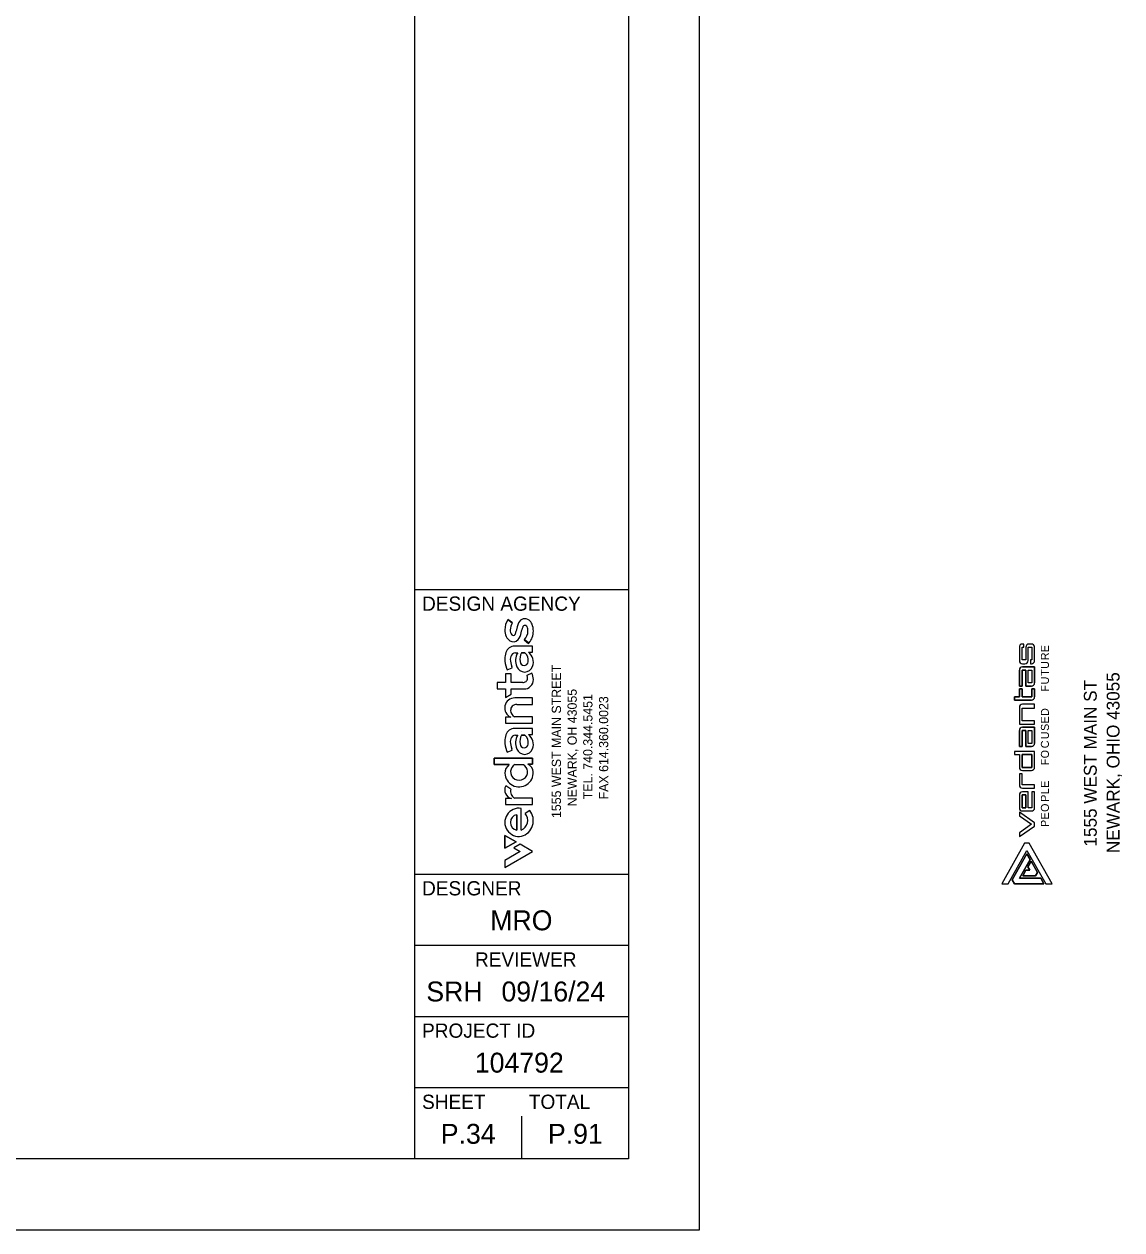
# Model space of a CAD drawing. Extents: x -0.2 to 37, y 0 to 22.
# Drawn here: x 29.25 to 36.97, y 0 to 8.47 of the extents above; entities that cross this region are included whole.
import ezdxf

# ---------------------------------------------------------------- set-up
doc = ezdxf.new("R2010")
doc.units = 0
for name, color, linetype in [('Default', 7, 'Continuous'), ('PF_P_Text_Curve', 7, 'Continuous'), ('SH_Border', 7, 'Continuous'), ('SH_Cut_Line', 7, 'Continuous'), ('SH_Data', 7, 'Continuous'), ('SH_Text', 7, 'Continuous')]:
    doc.layers.add(name, color=color, linetype=linetype)

msp = doc.modelspace()

# ---------------------------------------------------------------- linework, layer by layer
at = {"layer": 'Default'}
for p, q in [((36.2462, 4.0936), (36.2462, 4.0008)), ((36.3306, 4.1161), (36.3137, 4.1161)), ((36.3531, 4.0008), (36.3531, 4.0936)), ((36.2687, 3.9783), (36.2856, 3.9783)), ((36.2687, 3.2273), (36.3306, 3.2273)), ((36.2462, 3.0557), (36.2462, 2.9657)), ((36.2687, 2.9432), (36.3306, 2.9432)), ((36.1957, 2.4593), (36.299, 2.6425)), ((36.299, 2.6425), (36.3216, 2.6024)), ((36.3216, 2.6024), (36.2475, 2.471)), ((36.2113, 2.4316), (36.1957, 2.4593)), ((36.2475, 2.471), (36.3958, 2.471)), ((36.3958, 2.471), (36.418, 2.4316)), ((36.418, 2.4316), (36.2113, 2.4316))]:
    msp.add_line(p, q, dxfattribs=at)
for points in [[(36.2912, 4.0936), (36.2912, 4.0064), (36.2659, 4.0064), (36.2659, 4.0936), (36.2772, 4.0936), (36.2772, 4.1161), (36.2687, 4.1161)], [(36.3081, 4.0008), (36.3081, 4.0936), (36.3334, 4.0936), (36.3334, 4.0064), (36.325, 4.0064), (36.325, 3.9783), (36.3306, 3.9783)], [(36.2462, 3.9333), (36.2462, 3.8208), (36.2659, 3.8208), (36.2659, 3.9333), (36.2912, 3.9333), (36.2912, 3.8208), (36.3306, 3.8208)], [(36.3531, 3.8433), (36.3531, 3.9558), (36.2687, 3.9558)], [(36.3531, 3.7448), (36.3531, 3.801), (36.3334, 3.801), (36.3334, 3.7448), (36.2659, 3.7448), (36.2659, 3.801), (36.2462, 3.801), (36.2462, 3.7448), (36.2115, 3.7448), (36.2115, 3.7223), (36.3306, 3.7223)], [(36.2462, 3.6717), (36.2462, 3.5535), (36.3531, 3.5535), (36.3531, 3.576), (36.2659, 3.576), (36.2659, 3.666), (36.3531, 3.666), (36.3531, 3.6942), (36.2687, 3.6942)], [(36.2462, 3.5085), (36.2462, 3.396), (36.2659, 3.396), (36.2659, 3.5085), (36.2912, 3.5085), (36.2912, 3.396), (36.3306, 3.396)], [(36.3531, 3.4185), (36.3531, 3.531), (36.2687, 3.531)], [(36.3531, 3.2498), (36.3531, 3.3623), (36.2115, 3.3623), (36.2115, 3.3398), (36.2462, 3.3398), (36.2462, 3.2498)], [(36.2687, 3.1035), (36.3531, 3.1035), (36.3531, 3.126), (36.2659, 3.126), (36.2659, 3.2048), (36.2462, 3.2048), (36.2462, 3.126)], [(36.3531, 2.9657), (36.3531, 3.0782), (36.3334, 3.0782), (36.3334, 2.9657), (36.3081, 2.9657), (36.3081, 3.0782), (36.2687, 3.0782)]]:
    msp.add_lwpolyline(points, dxfattribs=at)
for points in [[(36.3334, 3.9333), (36.3334, 3.8433), (36.3081, 3.8433), (36.3081, 3.9333)], [(36.3334, 3.5085), (36.3334, 3.4185), (36.3081, 3.4185), (36.3081, 3.5085)], [(36.2659, 3.3398), (36.3334, 3.3398), (36.3334, 3.2498), (36.2659, 3.2498)], [(36.2912, 3.0557), (36.2912, 2.9657), (36.2659, 2.9657), (36.2659, 3.0557)], [(36.2462, 2.7903), (36.2462, 2.7629), (36.3531, 2.8377), (36.3536, 2.8609), (36.2467, 2.9357), (36.2462, 2.9086), (36.3307, 2.8495)], [(36.299, 2.6654), (36.4309, 2.4316), (36.4761, 2.4316), (36.3152, 2.7169), (36.2829, 2.7169), (36.122, 2.4316), (36.1672, 2.4316)], [(36.1672, 2.4316), (36.299, 2.6654), (36.4309, 2.4316), (36.4761, 2.4316), (36.3152, 2.7169), (36.2829, 2.7169), (36.122, 2.4316)], [(36.1957, 2.4593), (36.2113, 2.4316), (36.418, 2.4316), (36.3958, 2.471), (36.2475, 2.471), (36.3216, 2.6024), (36.299, 2.6425)], [(36.2921, 2.5272), (36.2699, 2.4878), (36.3603, 2.4878), (36.3733, 2.5108), (36.3281, 2.591), (36.3055, 2.5509), (36.3189, 2.5272)], [(36.2921, 2.5272), (36.3189, 2.5272), (36.3055, 2.5509), (36.3281, 2.591), (36.3733, 2.5108), (36.3603, 2.4878), (36.2699, 2.4878)]]:
    msp.add_lwpolyline(points, close=True, dxfattribs=at)
for centre, start, end in [((36.2687, 4.0936), 90, 180), ((36.3137, 4.0936), 90, 180), ((36.3306, 4.0936), 360, 90), ((36.2687, 4.0008), 180, 270), ((36.2856, 4.0008), 270, 0), ((36.3306, 4.0008), 270, 0), ((36.2687, 3.9333), 90, 180), ((36.3306, 3.8433), 270, 0), ((36.3306, 3.7448), 270, 0), ((36.2687, 3.6717), 90, 180), ((36.2687, 3.5085), 90, 180), ((36.3306, 3.4185), 270, 0), ((36.2687, 3.2498), 180, 270), ((36.3306, 3.2498), 270, 0), ((36.2687, 3.126), 180, 270), ((36.2687, 3.0557), 90, 180), ((36.2687, 2.9657), 180, 270), ((36.3306, 2.9657), 270, 0)]:
    msp.add_arc(centre, 0.0225, start, end, dxfattribs=at)
at = {"layer": 'PF_P_Text_Curve'}
for p, q in [((36.2462, 4.0936), (36.2462, 4.0008)), ((36.2772, 4.1161), (36.2687, 4.1161)), ((36.3306, 4.1161), (36.3137, 4.1161)), ((36.3531, 4.0008), (36.3531, 4.0936)), ((36.2462, 3.8208), (36.2462, 3.9333)), ((36.2687, 3.9783), (36.2856, 3.9783)), ((36.2462, 3.396), (36.2462, 3.5085)), ((36.2687, 3.2273), (36.3306, 3.2273)), ((36.2462, 3.0557), (36.2462, 2.9657)), ((36.3531, 2.9657), (36.3531, 3.0782)), ((36.2687, 2.9432), (36.3306, 2.9432))]:
    msp.add_line(p, q, dxfattribs=at)
for points in [[(36.2912, 4.0936), (36.2912, 4.0064), (36.2659, 4.0064), (36.2659, 4.0936), (36.2772, 4.0936), (36.2772, 4.1161)], [(36.3081, 4.0008), (36.3081, 4.0936), (36.3334, 4.0936), (36.3334, 4.0064), (36.325, 4.0064), (36.325, 3.9783), (36.3306, 3.9783)], [(36.3306, 3.8208), (36.2912, 3.8208), (36.2912, 3.9333), (36.2659, 3.9333), (36.2659, 3.8208), (36.2462, 3.8208)], [(36.2687, 3.9558), (36.3531, 3.9558), (36.3531, 3.8433)], [(36.2115, 3.7448), (36.2462, 3.7448), (36.2462, 3.801), (36.2659, 3.801), (36.2659, 3.7448), (36.3334, 3.7448), (36.3334, 3.801), (36.3531, 3.801), (36.3531, 3.7448)], [(36.3306, 3.7223), (36.2115, 3.7223), (36.2115, 3.7448)], [(36.2462, 3.6717), (36.2462, 3.5535), (36.3531, 3.5535), (36.3531, 3.576), (36.2659, 3.576), (36.2659, 3.666), (36.3531, 3.666)], [(36.3531, 3.666), (36.3531, 3.6942), (36.2687, 3.6942)], [(36.3306, 3.396), (36.2912, 3.396), (36.2912, 3.5085), (36.2659, 3.5085), (36.2659, 3.396), (36.2462, 3.396)], [(36.2687, 3.531), (36.3531, 3.531), (36.3531, 3.4185)], [(36.2115, 3.3623), (36.2115, 3.3398), (36.2462, 3.3398), (36.2462, 3.2498)], [(36.3531, 3.2498), (36.3531, 3.3623), (36.2115, 3.3623)], [(36.3531, 3.126), (36.2659, 3.126), (36.2659, 3.2048), (36.2462, 3.2048), (36.2462, 3.126)], [(36.2687, 3.1035), (36.3531, 3.1035), (36.3531, 3.126)], [(36.3531, 3.0782), (36.3334, 3.0782), (36.3334, 2.9657), (36.3081, 2.9657), (36.3081, 3.0782), (36.2687, 3.0782)]]:
    msp.add_lwpolyline(points, dxfattribs=at)
for points in [[(36.3081, 3.9333), (36.3334, 3.9333), (36.3334, 3.8433), (36.3081, 3.8433)], [(36.3081, 3.5085), (36.3334, 3.5085), (36.3334, 3.4185), (36.3081, 3.4185)], [(36.2659, 3.3398), (36.2659, 3.2498), (36.3334, 3.2498), (36.3334, 3.3398)], [(36.2912, 3.0557), (36.2659, 3.0557), (36.2659, 2.9657), (36.2912, 2.9657)], [(36.3307, 2.8495), (36.2462, 2.7903), (36.2462, 2.7629), (36.3531, 2.8377), (36.3536, 2.8609), (36.2467, 2.9357), (36.2462, 2.9086)]]:
    msp.add_lwpolyline(points, close=True, dxfattribs=at)
for centre, start, end in [((36.2687, 4.0936), 90, 180), ((36.3137, 4.0936), 90, 180), ((36.3306, 4.0936), 360, 90), ((36.2687, 4.0008), 180, 270), ((36.2856, 4.0008), 270, 0), ((36.3306, 4.0008), 270, 0), ((36.2687, 3.9333), 90, 180), ((36.3306, 3.8433), 270, 360), ((36.3306, 3.7448), 270, 360), ((36.2687, 3.6717), 90, 180), ((36.2687, 3.5085), 90, 180), ((36.3306, 3.4185), 270, 360), ((36.2687, 3.2498), 180, 270), ((36.3306, 3.2498), 270, 0), ((36.2687, 3.126), 180, 270), ((36.2687, 3.0557), 90, 180), ((36.2687, 2.9657), 180, 270), ((36.3306, 2.9657), 270, 0)]:
    msp.add_arc(centre, 0.0225, start, end, dxfattribs=at)
at = {"layer": 'SH_Border'}
for p, q in [((32, 0.5), (32, 21.5)), ((32, 4.5), (33.5, 4.5)), ((32, 2.5), (33.5, 2.5)), ((32, 2), (33.5, 2)), ((32, 1.5), (33.5, 1.5)), ((32, 1), (33.5, 1))]:
    msp.add_line(p, q, dxfattribs=at)
msp.add_lwpolyline([(1.5, 21.5), (33.5, 21.5), (33.5, 0.5), (1.5, 0.5)], close=True, dxfattribs=at)
at = {"layer": 'SH_Cut_Line'}
msp.add_lwpolyline([(0, 0), (34, 0), (34, 22), (0, 22)], close=True, dxfattribs=at)
at = {"layer": 'SH_Data'}
for p, q in [((32.75, 3.5), (32.75, 3.5)), ((32.75, 0.5), (32.75, 0.8)), ((32.375, 0.675), (32.375, 0.675))]:
    msp.add_line(p, q, dxfattribs=at)
at = {"layer": 'SH_Text'}
for p, q in [((32.6834, 4.2635), (32.6523, 4.2871)), ((32.7178, 4.2377), (32.711, 4.2066)), ((32.747, 4.1959), (32.7513, 4.2159)), ((32.7696, 4.148), (32.8023, 4.1242)), ((32.7069, 4.0554), (32.723, 4.0554)), ((32.7484, 4.0554), (32.7715, 4.0554)), ((32.6432, 3.9475), (32.6479, 3.9355)), ((32.8206, 3.9118), (32.7855, 3.8955)), ((32.7069, 3.4769), (32.723, 3.4769)), ((32.7484, 3.4769), (32.7715, 3.4769)), ((32.6432, 3.369), (32.6479, 3.357)), ((32.7014, 3.2687), (32.7618, 3.2687)), ((32.6742, 3.0974), (32.6373, 3.1197)), ((32.7163, 2.9168), (32.7163, 2.8096)), ((32.7465, 2.8087), (32.7465, 2.9618)), ((32.806, 2.9471), (32.7737, 2.9249))]:
    msp.add_line(p, q, dxfattribs=at)
for points in [[(32.6851, 4.2661), (32.6533, 4.2884), (32.6523, 4.2871)], [(32.6834, 4.2635), (32.6851, 4.2661)], [(32.7178, 4.2377), (32.711, 4.2066)], [(32.747, 4.1959), (32.7513, 4.2159)], [(32.7967, 4.0593), (32.8268, 4.0593), (32.8268, 4.1009), (32.7018, 4.1009)], [(32.7967, 4.0593), (32.8268, 4.0593), (32.8268, 4.1009), (32.7018, 4.1009)], [(32.7696, 4.148), (32.7673, 4.1455), (32.7988, 4.1205), (32.8023, 4.1242)], [(32.7069, 4.0554), (32.723, 4.0554)], [(32.7715, 4.0554), (32.7484, 4.0554)], [(32.7572, 3.8461), (32.6753, 3.8461), (32.6753, 3.9071), (32.6364, 3.9071), (32.6364, 3.8461), (32.578, 3.8461), (32.578, 3.8006), (32.6364, 3.8006), (32.6364, 3.7409), (32.6753, 3.7644), (32.6753, 3.8006), (32.7652, 3.8006)], [(32.7572, 3.8461), (32.6753, 3.8461), (32.6753, 3.9071), (32.6364, 3.9071), (32.6364, 3.8461), (32.578, 3.8461), (32.578, 3.8006), (32.6364, 3.8006), (32.6364, 3.7409), (32.6753, 3.7644), (32.6753, 3.8006), (32.7652, 3.8006)], [(32.6432, 3.9475), (32.6479, 3.9355)], [(32.6479, 3.9355), (32.6836, 3.95), (32.6798, 3.9594)], [(32.6479, 3.9355), (32.6836, 3.95), (32.6798, 3.9594)], [(32.8206, 3.9118), (32.7855, 3.8955)], [(32.7151, 3.6918), (32.8268, 3.6918), (32.8268, 3.7372), (32.7025, 3.7372)], [(32.7151, 3.6918), (32.8268, 3.6918), (32.8268, 3.7372), (32.7025, 3.7372)], [(32.6737, 3.6023), (32.6364, 3.6023), (32.6364, 3.5603), (32.8268, 3.5603), (32.8268, 3.6057), (32.6995, 3.6057)], [(32.6737, 3.6023), (32.6364, 3.6023), (32.6364, 3.5603), (32.8268, 3.5603), (32.8268, 3.6057), (32.6995, 3.6057)], [(32.7967, 3.4808), (32.8268, 3.4808), (32.8268, 3.5224), (32.7018, 3.5224)], [(32.7967, 3.4808), (32.8268, 3.4808), (32.8268, 3.5224), (32.7018, 3.5224)], [(32.7069, 3.4769), (32.723, 3.4769)], [(32.7715, 3.4769), (32.7484, 3.4769)], [(32.6626, 3.2687), (32.5556, 3.2687), (32.5556, 3.3141), (32.8268, 3.3141), (32.8268, 3.2725), (32.7933, 3.2725)], [(32.7933, 3.2725), (32.8268, 3.2725), (32.8268, 3.3141), (32.5556, 3.3141), (32.5556, 3.2687), (32.6626, 3.2687)], [(32.6432, 3.369), (32.6479, 3.357)], [(32.6479, 3.357), (32.6836, 3.3715), (32.6798, 3.3809)], [(32.6479, 3.357), (32.6836, 3.3715), (32.6798, 3.3809)], [(32.7014, 3.2687), (32.7618, 3.2687)], [(32.6742, 3.0974), (32.6373, 3.1197)], [(32.6771, 3.0301), (32.6363, 3.0301), (32.6363, 2.9887), (32.8267, 2.9887), (32.8267, 3.0326), (32.7006, 3.0326)], [(32.6771, 3.0301), (32.6363, 3.0301), (32.6363, 2.9887), (32.8267, 2.9887), (32.8267, 3.0326), (32.7006, 3.0326)], [(32.7163, 2.8096), (32.7163, 2.9168)], [(32.7465, 2.8087), (32.7465, 2.9618)], [(32.806, 2.9471), (32.7737, 2.9249)], [(32.6313, 2.7719), (32.6313, 2.6811), (32.71, 2.7265), (32.6313, 2.7719)], [(32.6952, 2.6849), (32.7398, 2.6592), (32.6313, 2.5965), (32.6313, 2.5465), (32.8266, 2.6592), (32.7386, 2.71), (32.6952, 2.6849)]]:
    msp.add_lwpolyline(points, dxfattribs=at)
for points in [[(32.71, 2.7265), (32.6313, 2.6811), (32.6313, 2.7719)], [(32.6952, 2.6849), (32.7398, 2.6592), (32.6313, 2.5965), (32.6313, 2.5465), (32.8266, 2.6592), (32.7386, 2.71)]]:
    msp.add_lwpolyline(points, close=True, dxfattribs=at)
for centre, radius, start, end in [((32.7627, 4.2161), 0.1313, 147.22328, 179.84204), ((32.7627, 4.2161), 0.1313, 147.22328, 179.84204), ((32.7639, 4.2134), 0.0948, 148.12326, 178.11353), ((32.7639, 4.2134), 0.0948, 148.12326, 178.11353), ((32.8442, 4.209), 0.1296, 154.04469, 167.21491), ((32.8442, 4.209), 0.1296, 154.04469, 167.21491), ((32.772, 4.2444), 0.0493, 52.70919, 154.21664), ((32.772, 4.2444), 0.0493, 52.70919, 154.21664), ((32.7727, 4.231), 0.0165, 26.91646, 163.60196), ((32.7727, 4.231), 0.0165, 26.91646, 163.60196), ((32.7287, 4.2095), 0.0655, 357.00773, 26.31116), ((32.7287, 4.2095), 0.0655, 357.00773, 26.31116), ((32.7569, 4.2285), 0.0711, 22.82777, 50.71565), ((32.7569, 4.2285), 0.0711, 22.82777, 50.71565), ((32.7122, 4.2095), 0.1196, 359.0192, 22.9257), ((32.7122, 4.2095), 0.1196, 359.0192, 22.9257), ((32.7453, 4.2145), 0.1139, 179.01095, 203.55998), ((32.7453, 4.2145), 0.1139, 179.01095, 203.55998), ((32.7024, 4.1955), 0.067, 203.36923, 237.807), ((32.7024, 4.1955), 0.067, 203.36923, 237.807), ((32.7393, 4.2154), 0.0702, 179.05393, 195.69208), ((32.7393, 4.2154), 0.0702, 179.05393, 195.69208), ((32.7043, 4.2044), 0.0335, 193.85614, 223.71908), ((32.7043, 4.2044), 0.0335, 193.85614, 223.71908), ((32.6906, 4.1917), 0.0148, 224.78223, 330.43657), ((32.6906, 4.1917), 0.0148, 224.78223, 330.43657), ((32.6306, 4.2217), 0.0819, 332.90022, 349.38313), ((32.6306, 4.2217), 0.0819, 332.90022, 349.38313), ((32.6434, 4.2147), 0.1053, 320.12588, 349.70225), ((32.6434, 4.2147), 0.1053, 320.12588, 349.70225), ((32.845, 4.2004), 0.0949, 158.18628, 170.63281), ((32.845, 4.2004), 0.0949, 158.18628, 170.63281), ((32.7011, 4.2111), 0.0932, 317.36304, 356.92436), ((32.7011, 4.2111), 0.0932, 317.36304, 356.92436), ((32.7024, 4.2065), 0.1295, 320.51657, 0.43409), ((32.7024, 4.2065), 0.1295, 320.51657, 0.43409), ((32.6996, 4.037), 0.0639, 88.07599, 162.86424), ((32.6996, 4.037), 0.0639, 88.07599, 162.86424), ((32.6903, 4.1781), 0.0458, 238.94525, 317.68291), ((32.6903, 4.1781), 0.0458, 238.94525, 317.68291), ((32.7597, 4.0137), 0.1283, 160.81276, 180.93166), ((32.7597, 4.0137), 0.1283, 160.81276, 180.93166), ((32.83, 4.0149), 0.1986, 180.9467, 199.83537), ((32.83, 4.0149), 0.1986, 180.9467, 199.83537), ((32.7347, 4.009), 0.0647, 163.25224, 179.99706), ((32.7347, 4.009), 0.0647, 163.25224, 179.99706), ((32.8215, 4.0134), 0.1516, 181.66161, 200.87137), ((32.8215, 4.0134), 0.1516, 181.66161, 200.87137), ((32.7089, 4.0181), 0.0374, 92.96709, 165.223), ((32.7089, 4.0181), 0.0374, 92.96709, 165.223), ((32.8153, 3.9985), 0.1085, 148.34975, 202.47075), ((32.8153, 3.9985), 0.1085, 148.34975, 202.47075), ((32.8425, 4.0092), 0.1048, 153.83718, 188.87457), ((32.8425, 4.0092), 0.1048, 153.83718, 188.87457), ((32.767, 3.9942), 0.0281, 182.32704, 355.37776), ((32.767, 3.9942), 0.0281, 182.32704, 355.37776), ((32.7327, 4.005), 0.0637, 348.12474, 52.36783), ((32.7327, 4.005), 0.0637, 348.12474, 52.36783), ((32.7461, 3.9901), 0.0857, 338.27739, 53.79489), ((32.7461, 3.9901), 0.0857, 338.27739, 53.79489), ((32.7701, 3.9789), 0.0592, 201.67635, 339.72677), ((32.7701, 3.9789), 0.0592, 201.67635, 339.72677), ((32.7379, 3.8674), 0.0939, 359.5424, 28.24947), ((32.7379, 3.8674), 0.0939, 359.5424, 28.24947), ((32.7599, 3.8774), 0.0314, 265.06923, 356.35481), ((32.7599, 3.8774), 0.0314, 265.06923, 356.35481), ((32.7676, 3.8648), 0.0642, 267.86409, 1.62134), ((32.7676, 3.8648), 0.0642, 267.86409, 1.62134), ((32.7481, 3.874), 0.0432, 1.86376, 29.96515), ((32.7481, 3.874), 0.0432, 1.86376, 29.96515), ((32.7013, 3.667), 0.0703, 88.98961, 246.91113), ((32.7013, 3.667), 0.0703, 88.98961, 246.91113), ((32.7154, 3.6509), 0.0434, 137.30492, 182.96879), ((32.7154, 3.6509), 0.0434, 137.30492, 182.96879), ((32.7197, 3.649), 0.0477, 180.34657, 244.91134), ((32.7197, 3.649), 0.0477, 180.34657, 244.91134), ((32.7129, 3.6485), 0.0433, 86.97388, 132.7421), ((32.7129, 3.6485), 0.0433, 86.97388, 132.7421), ((32.7597, 3.4352), 0.1283, 160.81276, 180.93166), ((32.7597, 3.4352), 0.1283, 160.81276, 180.93166), ((32.6996, 3.4585), 0.0639, 88.07599, 162.86424), ((32.6996, 3.4585), 0.0639, 88.07599, 162.86424), ((32.7089, 3.4396), 0.0374, 92.96709, 165.223), ((32.7089, 3.4396), 0.0374, 92.96709, 165.223), ((32.8153, 3.42), 0.1085, 148.34975, 202.47075), ((32.8153, 3.42), 0.1085, 148.34975, 202.47075), ((32.8425, 3.4307), 0.1048, 153.83718, 188.87457), ((32.8425, 3.4307), 0.1048, 153.83718, 188.87457), ((32.7327, 3.4265), 0.0637, 348.12474, 52.36783), ((32.7327, 3.4265), 0.0637, 348.12474, 52.36783), ((32.7461, 3.4116), 0.0857, 338.27739, 53.79489), ((32.7461, 3.4116), 0.0857, 338.27739, 53.79489), ((32.83, 3.4364), 0.1986, 180.9467, 199.83537), ((32.83, 3.4364), 0.1986, 180.9467, 199.83537), ((32.7347, 3.4305), 0.0647, 163.25224, 179.99706), ((32.7347, 3.4305), 0.0647, 163.25224, 179.99706), ((32.8215, 3.4349), 0.1516, 181.66161, 200.87137), ((32.8215, 3.4349), 0.1516, 181.66161, 200.87137), ((32.767, 3.4157), 0.0281, 182.32704, 355.37776), ((32.767, 3.4157), 0.0281, 182.32704, 355.37776), ((32.7701, 3.4004), 0.0592, 201.67635, 339.72677), ((32.7701, 3.4004), 0.0592, 201.67635, 339.72677), ((32.7028, 3.2097), 0.0714, 124.28433, 181.27226), ((32.7028, 3.2097), 0.0714, 124.28433, 181.27226), ((32.7316, 3.2187), 0.0595, 176.4529, 5.05495), ((32.7316, 3.2187), 0.0595, 176.4529, 5.05495), ((32.7306, 3.2179), 0.0586, 119.90067, 175.57974), ((32.7306, 3.2179), 0.0586, 119.90067, 175.57974), ((32.7324, 3.2177), 0.0588, 6.06662, 60.04101), ((32.7324, 3.2177), 0.0588, 6.06662, 60.04101), ((32.7645, 3.2119), 0.0671, 5.30838, 64.52521), ((32.7645, 3.2119), 0.0671, 5.30838, 64.52521), ((32.7314, 3.2129), 0.1001, 182.77189, 2.9779), ((32.7314, 3.2129), 0.1001, 182.77189, 2.9779), ((32.6931, 3.0909), 0.0628, 152.6524, 255.29294), ((32.6931, 3.0909), 0.0628, 152.6524, 255.29294), ((32.7261, 3.0807), 0.0545, 162.13838, 242.04081), ((32.7261, 3.0807), 0.0545, 162.13838, 242.04081), ((32.731, 2.8634), 0.0996, 81.04458, 280.25771), ((32.731, 2.8634), 0.0996, 81.04458, 280.25771), ((32.7246, 2.8632), 0.0543, 98.83779, 261.16221), ((32.7246, 2.8632), 0.0543, 98.83779, 261.16221), ((32.7208, 2.876), 0.072, 290.92317, 42.73906), ((32.7208, 2.876), 0.072, 290.92317, 42.73906), ((32.718, 2.8749), 0.1138, 285.66678, 39.36993), ((32.718, 2.8749), 0.1138, 285.66678, 39.36993)]:
    msp.add_arc(centre, radius, start, end, dxfattribs=at)

# ---------------------------------------------------------------- texts
at = {"layer": 'Default'}
for s, p in [('E', (36.4538, 4.0587)), ('R', (36.4538, 4.0029)), ('U', (36.4538, 3.942)), ('T', (36.4538, 3.8934)), ('U', (36.4538, 3.8326)), ('F', (36.4538, 3.7813)), ('D', (36.4538, 3.6111)), ('E', (36.4538, 3.5583)), ('S', (36.4538, 3.5057)), ('U', (36.4538, 3.4472)), ('C', (36.4538, 3.3841)), ('O', (36.4538, 3.313)), ('F', (36.4538, 3.2641)), ('E', (36.4538, 3.106)), ('L', (36.4538, 3.0607)), ('P', (36.4538, 3.008)), ('O', (36.4538, 2.9367)), ('E', (36.4538, 2.8837)), ('P', (36.4538, 2.8309))]:
    msp.add_text(s, height=0.0563, rotation=90, dxfattribs=at).set_placement(p)
at = {"layer": 'SH_Data'}
for s, height, p in [('DESIGN AGENCY', 0.1, (32.05, 4.35)), ('DESIGNER', 0.1, (32.05, 2.35)), ('MRO', 0.14, (32.5292, 2.105)), ('REVIEWER', 0.1, (32.4218, 1.85)), ('SRH', 0.14, (32.08, 1.605)), ('09/16/24', 0.14, (32.6078, 1.605)), ('PROJECT ID', 0.1, (32.05, 1.35)), ('104792', 0.14, (32.4209, 1.105)), ('SHEET', 0.1, (32.05, 0.85)), ('TOTAL', 0.1, (32.8, 0.85)), ('P.34', 0.14, (32.1816, 0.605)), ('P.91', 0.14, (32.9344, 0.605))]:
    msp.add_text(s, height=height, dxfattribs=at).set_placement(p)
at = {"layer": 'SH_Text'}
for s, height, p in [('1555 WEST MAIN STREET', 0.064969, (33.0262, 2.8937)), ('NEWARK, OHIO 43055', 0.09, (36.9496, 2.6472)), ('1555 WEST MAIN ST', 0.09, (36.7896, 2.6934)), ('NEWARK, OH 43055', 0.064969, (33.1367, 2.9756)), ('TEL. 740.344.5451', 0.064969, (33.247, 3.0253)), ('FAX 614.360.0023', 0.064969, (33.3577, 3.0247))]:
    msp.add_text(s, height=height, rotation=90, dxfattribs=at).set_placement(p)

doc.saveas('drawing.dxf')
